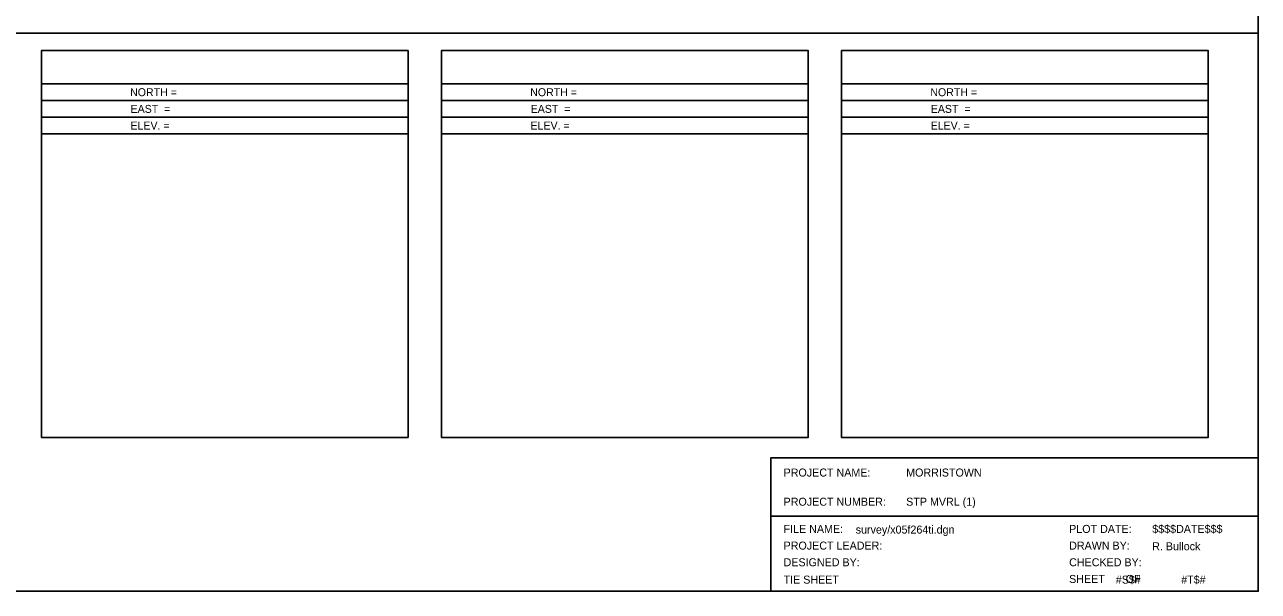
# Model space of a CAD drawing. Extents: x 1612431 to 1613071, y 750572 to 750992.
# Drawn here: x 1612701.1 to 1613071.1, y 750572.1 to 750742 of the extents above; entities that cross this region are included whole.
import ezdxf

# ---------------------------------------------------------------- set-up
doc = ezdxf.new("R2010")
doc.units = 0
doc.layers.add('NBL2', color=7, linetype='Continuous')

msp = doc.modelspace()

# ---------------------------------------------------------------- linework, layer by layer
at = {"layer": 'NBL2'}
for p, q in [((1612431.13, 750739.46), (1613071.13, 750739.46)), ((1612816.13, 750724.3), (1612706.13, 750724.3)), ((1612936.13, 750724.3), (1612826.13, 750724.3)), ((1613056.13, 750724.3), (1612946.13, 750724.3)), ((1612816.13, 750719.3), (1612706.13, 750719.3)), ((1612936.13, 750719.3), (1612826.13, 750719.3)), ((1613056.13, 750719.3), (1612946.13, 750719.3)), ((1612816.13, 750714.3), (1612706.13, 750714.3)), ((1612936.13, 750714.3), (1612826.13, 750714.3)), ((1613056.13, 750714.3), (1612946.13, 750714.3)), ((1612816.13, 750709.3), (1612706.13, 750709.3)), ((1612936.13, 750709.3), (1612826.13, 750709.3)), ((1613056.13, 750709.3), (1612946.13, 750709.3)), ((1612924.88, 750594.63), (1613071.13, 750594.63))]:
    msp.add_line(p, q, dxfattribs=at)
for points in [[(1612431.13, 750572.13), (1613071.13, 750572.13), (1613071.13, 750992.13), (1612431.13, 750992.13)], [(1612706.13, 750618.3), (1612816.13, 750618.3), (1612816.13, 750734.3), (1612706.13, 750734.3)], [(1612826.13, 750618.3), (1612936.13, 750618.3), (1612936.13, 750734.3), (1612826.13, 750734.3)], [(1612946.13, 750618.3), (1613056.13, 750618.3), (1613056.13, 750734.3), (1612946.13, 750734.3)]]:
    msp.add_lwpolyline(points, close=True, dxfattribs=at)
msp.add_lwpolyline([(1613071.13, 750612.13), (1612924.88, 750612.13), (1612924.88, 750572.13)], dxfattribs=at)

# ---------------------------------------------------------------- texts
for s, height, p in [('NORTH =             ', 2.375, (1612732.75, 750720.61)), ('NORTH =             ', 2.375, (1612852.75, 750720.61)), ('NORTH =             ', 2.375, (1612972.75, 750720.61)), ('EAST  =             ', 2.375, (1612732.89, 750715.61)), ('EAST  =             ', 2.375, (1612852.89, 750715.61)), ('EAST  =             ', 2.375, (1612972.89, 750715.61)), ('ELEV. =             ', 2.375, (1612732.85, 750710.61)), ('ELEV. =             ', 2.375, (1612852.85, 750710.61)), ('ELEV. =             ', 2.375, (1612972.85, 750710.61)), ('PROJECT NAME:', 2.4, (1612928.75, 750606.55)), ('MORRISTOWN                                 ', 2.4, (1612965.51, 750606.55)), ('PROJECT NUMBER:', 2.4, (1612928.75, 750597.8)), ('STP MVRL (1)                               ', 2.4, (1612965.51, 750597.8)), ('FILE NAME:', 2.4, (1612928.75, 750589.64)), ('survey/x05f264ti.dgn      ', 2.4, (1612950.38, 750589.44)), ('PLOT DATE:', 2.4, (1613014.39, 750589.64)), ('$$$$DATE$$$', 2.4, (1613039.32, 750589.64)), ('PROJECT LEADER:', 2.4, (1612928.75, 750584.64)), ('DRAWN BY:', 2.4, (1613014.39, 750584.64)), ('R. Bullock   ', 2.4, (1613039.3, 750584.44)), ('DESIGNED BY:', 2.4, (1612928.75, 750579.64)), ('CHECKED BY:', 2.4, (1613014.39, 750579.64)), ('TIE SHEET                         ', 2.4, (1612928.75, 750574.44)), ('SHEET       OF', 2.4, (1613014.39, 750574.64)), ('#S$# ', 2.4, (1613028.38, 750574.44)), ('#T$#   ', 2.4, (1613048, 750574.44))]:
    msp.add_text(s, height=height, dxfattribs=at).set_placement(p)

doc.saveas('drawing.dxf')
